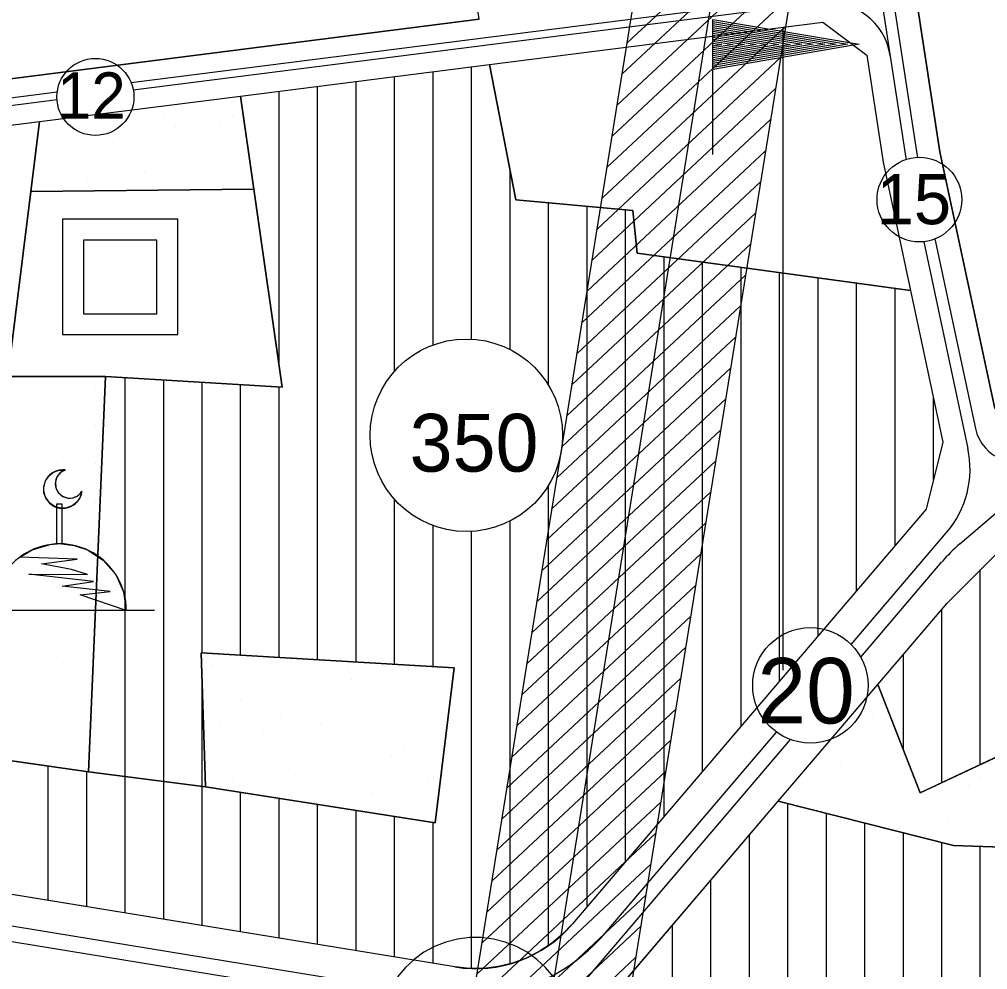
# Model space of a CAD drawing. Extents: x 419109 to 421295, y 4452223 to 4457798.
# Drawn here: x 419425.3 to 419676.8, y 4453192 to 4453438.7 of the extents above; entities that cross this region are included whole.
import ezdxf

# ---------------------------------------------------------------- set-up
doc = ezdxf.new("R2010")
doc.units = 0
for name, color, linetype in [('ADA', 7, 'Continuous'), ('ADAKENARI', 7, 'Continuous'), ('Default', 7, 'Continuous'), ('KALDIRIM', 7, 'Continuous'), ('KD_DAIRE', 7, 'Continuous'), ('KD_KAV_25', 7, 'Continuous'), ('KD_YGEN', 7, 'Continuous'), ('LJ_SEMBOL', 7, 'Continuous'), ('PL_AYA_PARK_DINLENME', 7, 'Continuous'), ('PL_KON_MEV_350', 7, 'Continuous'), ('PL_OZEL_DONATI', 7, 'Continuous'), ('PL_SAY_DINI_TESIS', 7, 'Continuous'), ('PL_SAY_SPOR', 7, 'Continuous'), ('SM_DAIRE', 7, 'Continuous'), ('SM_TAKS', 7, 'Continuous'), ('TA_ENH_154', 7, 'Continuous'), ('TA_ENH_KORUMA', 7, 'Continuous'), ('TA_ENH_TARAMA', 7, 'Continuous'), ('TR_DINITESIS', 7, 'Continuous'), ('TR_KENTSELSPOR', 7, 'Continuous'), ('TR_ORTAYOGUNKONUT', 7, 'Continuous'), ('TR_PARKALANI', 7, 'Continuous'), ('TR_PAZARLAMAAL', 7, 'Continuous'), ('TR_SAGLIKTESIS', 7, 'Continuous')]:
    doc.layers.add(name, color=color, linetype=linetype)

# ---------------------------------------------------------------- blocks, each defined once
blk = doc.blocks.new('POINT_DISPLAY')
at = {"layer": 'Default'}
blk.add_line((0, 0), (0, 0), dxfattribs=at)

msp = doc.modelspace()

# ---------------------------------------------------------------- linework, layer by layer
at = {"layer": 'ADA'}
for p, q in [((419547.38, 4453427.04), (419554.29, 4453391.85)), ((419486.2, 4453394.64), (419482.74, 4453418.83)), ((419430.49, 4453412.19), (419428.24, 4453394.01)), ((419428.24, 4453394.01), (419422.29, 4453346.02)), ((419428.24, 4453394.01), (419486.2, 4453394.64)), ((419493.54, 4453343.25), (419486.2, 4453394.64)), ((419554.29, 4453391.85), (419584.66, 4453389.09)), ((419584.66, 4453389.09), (419585.77, 4453378.05)), ((419585.77, 4453378.05), (419656.81, 4453368.31)), ((419447.7, 4453346.02), (419422.29, 4453346.02)), ((419443.28, 4453243.29), (419447.7, 4453346.02)), ((419447.7, 4453346.02), (419493.54, 4453343.25)), ((419538.27, 4453270.35), (419472.55, 4453274.22)), ((419472.55, 4453274.22), (419473.66, 4453239.43)), ((419533.3, 4453230.04), (419538.27, 4453270.35)), ((419648.28, 4453265.99), (419659.31, 4453237.86)), ((419659.31, 4453237.86), (419709.93, 4453261.66)), ((419405.17, 4453248.82), (419443.28, 4453243.29)), ((419473.66, 4453239.43), (419533.3, 4453230.04)), ((419667.92, 4453224.2), (419622.45, 4453235.7)), ((419710.94, 4453222.68), (419667.92, 4453224.2))]:
    msp.add_line(p, q, dxfattribs=at)
at = {"layer": 'ADAKENARI'}
for p, q in [((419664.45, 4453404.34), (419647.77, 4453512.81)), ((419544.76, 4453438.8), (419405.96, 4453421.17)), ((419547.38, 4453427.04), (419633.98, 4453438.04)), ((419633.98, 4453438.04), (419645.42, 4453429.42)), ((419645.42, 4453429.42), (419649.69, 4453401.63)), ((419482.74, 4453418.83), (419547.38, 4453427.04)), ((419430.49, 4453412.19), (419482.74, 4453418.83)), ((419407.47, 4453409.27), (419430.49, 4453412.19)), ((419678.69, 4453337.65), (419664.45, 4453404.34)), ((419649.69, 4453401.63), (419656.81, 4453368.31)), ((419656.81, 4453368.31), (419665.22, 4453328.9)), ((419665.22, 4453328.9), (419660.82, 4453311.51)), ((419660.82, 4453311.51), (419569.02, 4453203.86)), ((419666.3, 4453287.11), (419680.39, 4453301.22)), ((419648.28, 4453265.99), (419666.3, 4453287.11)), ((419622.45, 4453235.7), (419648.28, 4453265.99)), ((419538.42, 4453192.65), (419256.32, 4453238.73)), ((419512.36, 4453106.6), (419622.45, 4453235.7))]:
    msp.add_line(p, q, dxfattribs=at)
msp.add_arc((419543.77, 4453225.39), 33.18, 260.7236, 319.5427, dxfattribs=at)
at = {"layer": 'KALDIRIM'}
for p, q in [((419633.73, 4453564.67), (419658.55, 4453403.26)), ((419646.18, 4453463.94), (419655.59, 4453402.72)), ((419631.77, 4453444.81), (419454.34, 4453422.28)), ((419633.37, 4453443), (419454.89, 4453420.33)), ((419435.12, 4453419.84), (419406.59, 4453416.21)), ((419435.07, 4453417.81), (419406.84, 4453414.23)), ((419655.59, 4453402.72), (419655.66, 4453402.39)), ((419658.55, 4453403.26), (419658.62, 4453402.93)), ((419660.23, 4453381), (419671.69, 4453327.31)), ((419663.15, 4453381.71), (419673.65, 4453332.51)), ((419669.61, 4453302.53), (419750.92, 4453372.07)), ((419641.39, 4453276.4), (419666.16, 4453305.44)), ((419643.87, 4453273.14), (419664.97, 4453297.89)), ((419577.44, 4453201.41), (419621.99, 4453253.65)), ((419505.73, 4453111.15), (419625.6, 4453251.72)), ((419389.85, 4453208.81), (419533.58, 4453185.33)), ((419389.63, 4453204.79), (419519.06, 4453183.65))]:
    msp.add_line(p, q, dxfattribs=at)
for centre, radius, start, end in [((419635.42, 4453426.87), 16.27, 8.7413, 97.2392), ((419684.35, 4453334.79), 10.94, 192.0528, 310.5385), ((419646.76, 4453321.99), 25.5, 319.5427, 12.0528), ((419696.78, 4453270.77), 41.8, 130.5385, 139.5427), ((419541.25, 4453232.27), 47.56, 260.7236, 319.5427)]:
    msp.add_arc(centre, radius, start, end, dxfattribs=at)
at = {"layer": 'KD_DAIRE'}
for centre, radius in [((419445.04, 4453418.6), 10), ((419659.09, 4453391.94), 11), ((419630.79, 4453265.79), 15)]:
    msp.add_circle(centre, radius, dxfattribs=at)
at = {"layer": 'KD_KAV_25'}
for p, q in [((419539.1, 4453199.91), (419536.06, 4453199.13)), ((419542.21, 4453200.31), (419539.1, 4453199.91)), ((419545.35, 4453200.31), (419542.21, 4453200.31)), ((419548.47, 4453199.91), (419545.35, 4453200.31)), ((419551.51, 4453199.13), (419548.47, 4453199.91)), ((419533.14, 4453197.98), (419530.39, 4453196.46)), ((419536.06, 4453199.13), (419533.14, 4453197.98)), ((419554.43, 4453197.98), (419551.51, 4453199.13)), ((419557.18, 4453196.46), (419554.43, 4453197.98)), ((419530.39, 4453196.46), (419527.85, 4453194.62)), ((419559.72, 4453194.62), (419557.18, 4453196.46)), ((419525.56, 4453192.47), (419523.56, 4453190.05)), ((419527.85, 4453194.62), (419525.56, 4453192.47)), ((419562.01, 4453192.47), (419559.72, 4453194.62)), ((419564.01, 4453190.05), (419562.01, 4453192.47))]:
    msp.add_line(p, q, dxfattribs=at)
at = {"layer": 'LJ_SEMBOL'}
for p, q in [((419605.47, 4453403.68), (419605.47, 4453438.68)), ((419436.48, 4453386.86), (419436.48, 4453356.86)), ((419466.48, 4453386.86), (419436.48, 4453386.86)), ((419466.48, 4453356.86), (419466.48, 4453386.86)), ((419461.03, 4453381.4), (419441.94, 4453381.4)), ((419441.94, 4453381.4), (419441.94, 4453362.31)), ((419461.03, 4453362.31), (419461.03, 4453381.4)), ((419441.94, 4453362.31), (419461.03, 4453362.31)), ((419436.48, 4453356.86), (419466.48, 4453356.86)), ((419460.38, 4453285.21), (419413.71, 4453285.21))]:
    msp.add_line(p, q, dxfattribs=at)
for points in [[(419605.47, 4453438.68), (419643.42, 4453432.3), (419605.47, 4453425.73)], [(419605.47, 4453438.17), (419640.45, 4453432.29), (419605.47, 4453426.23)], [(419605.47, 4453437.66), (419637.47, 4453432.28), (419605.47, 4453426.74)], [(419605.47, 4453437.16), (419634.5, 4453432.28), (419605.47, 4453427.25)], [(419605.47, 4453436.65), (419631.53, 4453432.27), (419605.47, 4453427.76)], [(419605.47, 4453436.14), (419628.56, 4453432.26), (419605.47, 4453428.26)], [(419605.47, 4453435.64), (419625.59, 4453432.25), (419605.47, 4453428.77)], [(419605.47, 4453435.13), (419622.61, 4453432.25), (419605.47, 4453429.28)], [(419605.47, 4453434.62), (419619.64, 4453432.24), (419605.47, 4453429.79)], [(419605.47, 4453434.12), (419616.67, 4453432.23), (419605.47, 4453430.29)], [(419605.47, 4453433.61), (419613.7, 4453432.23), (419605.47, 4453430.8)], [(419605.47, 4453433.1), (419610.72, 4453432.22), (419605.47, 4453431.31)], [(419605.47, 4453432.59), (419607.75, 4453432.21), (419605.47, 4453431.82)]]:
    msp.add_lwpolyline(points, dxfattribs=at)
for points in [[(419436.48, 4453356.86), (419466.48, 4453356.86), (419466.48, 4453386.86), (419436.48, 4453386.86)], [(419441.55, 4453316.17), (419441.13, 4453314.66), (419440.26, 4453313.36), (419439.03, 4453312.39), (419437.56, 4453311.85), (419435.99, 4453311.79), (419434.48, 4453312.22), (419433.18, 4453313.09), (419432.22, 4453314.32), (419431.68, 4453315.79), (419431.62, 4453317.36), (419432.06, 4453318.87), (419432.93, 4453320.16), (419434.17, 4453321.13), (419435.64, 4453321.66), (419437.21, 4453321.71), (419435.95, 4453321.02), (419435.05, 4453319.91), (419434.64, 4453318.54), (419434.76, 4453317.11), (419435.41, 4453315.83), (419436.5, 4453314.89), (419437.85, 4453314.43), (419439.28, 4453314.51), (419440.58, 4453315.12)], [(419453.07, 4453285.22), (419441.09, 4453289.27), (419448.88, 4453290.19), (419436.44, 4453291.5), (419444.53, 4453292.76), (419427.78, 4453294.64), (419443.03, 4453294.57), (419438.86, 4453295.88), (419431.08, 4453297.32), (419440.3, 4453298.57), (419425.41, 4453299.09), (419428.58, 4453300.96), (419433.3, 4453302.35), (419435.05, 4453302.51), (419435.05, 4453312.93), (419436.3, 4453312.93), (419436.3, 4453302.52), (419439.54, 4453302.11), (419442.95, 4453300.96), (419447.1, 4453298.3), (419450.32, 4453294.58), (419452.37, 4453290.1)]]:
    msp.add_lwpolyline(points, close=True, dxfattribs=at)
for centre, radius, start, end in [((419436.59, 4453316.75), 5, 82.8556, 353.3219), ((419438.36, 4453318.15), 3.75, 107.9671, 328.2104), ((419435.77, 4453285.22), 17.31, 359.967, 180)]:
    msp.add_arc(centre, radius, start, end, dxfattribs=at)
at = {"layer": 'PL_AYA_PARK_DINLENME'}
for points in [[(419486.2, 4453394.64), (419428.24, 4453394.01), (419430.49, 4453412.19), (419482.74, 4453418.83)], [(419472.55, 4453274.22), (419538.27, 4453270.35), (419533.3, 4453230.04), (419473.66, 4453239.43)], [(419648.28, 4453265.99), (419659.31, 4453237.86), (419709.93, 4453261.66), (419710.94, 4453222.68), (419667.92, 4453224.2), (419622.45, 4453235.7)]]:
    msp.add_lwpolyline(points, close=True, dxfattribs=at)
at = {"layer": 'PL_KON_MEV_350'}
for points in [[(419665.01, 4453582.82), (419673.75, 4453518.14), (419647.77, 4453512.81), (419664.45, 4453404.34), (419678.69, 4453337.65), (419688.38, 4453334.37), (419743.12, 4453381.19)], [(419405.96, 4453421.17), (419544.76, 4453438.8), (419536.73, 4453492.22), (419575.78, 4453497.8), (419579.95, 4453471.41), (419597.04, 4453473.65), (419594.42, 4453493.65), (419591.8, 4453513.65), (419589.18, 4453533.65), (419587.39, 4453547.37), (419586.56, 4453553.65)], [(419405.17, 4453248.82), (419443.28, 4453243.29), (419473.66, 4453239.43), (419533.3, 4453230.04), (419538.27, 4453270.35), (419472.55, 4453274.22), (419473.66, 4453239.43), (419443.28, 4453243.29), (419447.7, 4453346.02), (419493.54, 4453343.25), (419486.2, 4453394.64), (419482.74, 4453418.83), (419547.38, 4453427.04), (419554.29, 4453391.85), (419584.66, 4453389.09), (419585.77, 4453378.05), (419656.81, 4453368.31), (419665.22, 4453328.9), (419660.82, 4453311.51), (419569.02, 4453203.86), (419566.4, 4453201.13), (419563.5, 4453198.71), (419560.33, 4453196.64), (419556.95, 4453194.94), (419553.4, 4453193.64), (419549.72, 4453192.75), (419545.97, 4453192.29), (419542.19, 4453192.25), (419538.42, 4453192.65), (419256.32, 4453238.73)], [(419407.47, 4453409.27), (419430.49, 4453412.19), (419428.24, 4453394.01), (419422.29, 4453346.02)], [(419709.93, 4453261.66), (419659.31, 4453237.86), (419648.28, 4453265.99), (419666.3, 4453287.11), (419680.39, 4453301.22)], [(419464.93, 4453019.07), (419512.36, 4453106.6), (419622.45, 4453235.7), (419667.92, 4453224.2), (419710.94, 4453222.68)]]:
    msp.add_lwpolyline(points, dxfattribs=at)
at = {"layer": 'PL_OZEL_DONATI'}
msp.add_lwpolyline([(419486.2, 4453394.64), (419493.54, 4453343.25), (419447.7, 4453346.02), (419422.29, 4453346.02), (419428.24, 4453394.01)], close=True, dxfattribs=at)
at = {"layer": 'PL_SAY_DINI_TESIS'}
msp.add_lwpolyline([(419447.7, 4453346.02), (419443.28, 4453243.29), (419405.17, 4453248.82), (419422.29, 4453346.02)], close=True, dxfattribs=at)
at = {"layer": 'PL_SAY_SPOR'}
msp.add_lwpolyline([(419547.38, 4453427.04), (419633.98, 4453438.04), (419645.42, 4453429.42), (419649.69, 4453401.63), (419656.81, 4453368.31), (419585.77, 4453378.05), (419584.66, 4453389.09), (419554.29, 4453391.85)], close=True, dxfattribs=at)
at = {"layer": 'SM_DAIRE'}
msp.add_circle((419541.41, 4453330.73), 25, dxfattribs=at)
at = {"layer": 'TA_ENH_154'}
msp.add_lwpolyline([(421244.23, 4452871.73), (420603.45, 4452866.93), (420104.11, 4452747.15), (419709.07, 4452649.72), (419353.3, 4452559.56), (419284.53, 4452601.29), (419287.68, 4452599.87), (419484.08, 4452691.72), (419833.95, 4454863.94), (419862.83, 4455014.24)], dxfattribs=at)
at = {"layer": 'TA_ENH_KORUMA'}
msp.add_line((419466.02, 4452705.35), (419814.25, 4454867.42), dxfattribs=at)
msp.add_lwpolyline([(419883.15, 4455014.02), (419853.65, 4454860.46), (419502.14, 4452678.09), (419329.55, 4452597.37), (419356.51, 4452581.01), (419704.22, 4452669.12), (420099.38, 4452766.58), (420601.01, 4452886.92), (421244.44, 4452891.74)], dxfattribs=at)
at = {"layer": 'TA_ENH_TARAMA'}
for p, q in [((419583.14, 4453432.57), (419630.84, 4453477.15)), ((419581.84, 4453424.52), (419629.54, 4453469.1)), ((419580.55, 4453416.46), (419628.25, 4453461.04)), ((419579.25, 4453408.4), (419626.95, 4453452.98)), ((419577.95, 4453400.35), (419625.65, 4453444.92)), ((419576.65, 4453392.29), (419624.35, 4453436.87)), ((419575.36, 4453384.23), (419623.05, 4453428.81)), ((419574.06, 4453376.17), (419621.76, 4453420.75)), ((419572.76, 4453368.12), (419620.46, 4453412.7)), ((419571.46, 4453360.06), (419619.16, 4453404.64)), ((419570.16, 4453352), (419617.86, 4453396.58)), ((419568.87, 4453343.95), (419616.57, 4453388.52)), ((419567.57, 4453335.89), (419615.27, 4453380.47)), ((419566.27, 4453327.83), (419613.97, 4453372.41)), ((419564.97, 4453319.77), (419612.67, 4453364.35)), ((419563.68, 4453311.72), (419611.38, 4453356.3)), ((419562.38, 4453303.66), (419610.08, 4453348.24)), ((419561.08, 4453295.6), (419608.78, 4453340.18)), ((419559.78, 4453287.55), (419607.48, 4453332.12)), ((419558.49, 4453279.49), (419606.18, 4453324.07)), ((419557.19, 4453271.43), (419604.89, 4453316.01)), ((419555.89, 4453263.37), (419603.59, 4453307.95)), ((419554.59, 4453255.32), (419602.29, 4453299.9)), ((419553.29, 4453247.26), (419600.99, 4453291.84)), ((419552, 4453239.2), (419599.7, 4453283.78)), ((419550.7, 4453231.15), (419598.4, 4453275.72)), ((419549.4, 4453223.09), (419597.1, 4453267.67)), ((419548.1, 4453215.03), (419595.8, 4453259.61)), ((419546.81, 4453206.97), (419594.51, 4453251.55)), ((419545.51, 4453198.92), (419593.21, 4453243.5)), ((419544.21, 4453190.86), (419591.91, 4453235.44)), ((419542.91, 4453182.8), (419590.61, 4453227.38)), ((419541.61, 4453174.75), (419589.31, 4453219.32)), ((419540.32, 4453166.69), (419588.02, 4453211.27)), ((419539.02, 4453158.63), (419586.72, 4453203.21)), ((419537.72, 4453150.57), (419585.42, 4453195.15))]:
    msp.add_line(p, q, dxfattribs=at)
at = {"layer": 'TR_ORTAYOGUNKONUT'}
for p, q in [((419542.78, 4453355.69), (419542.78, 4453426.46)), ((419522.78, 4453347.4), (419522.78, 4453423.91)), ((419532.78, 4453354.19), (419532.78, 4453425.18)), ((419502.78, 4453272.44), (419502.78, 4453421.37)), ((419512.78, 4453271.85), (419512.78, 4453422.64)), ((419492.78, 4453348.56), (419492.78, 4453420.1)), ((419552.78, 4453352.99), (419552.78, 4453399.53)), ((419562.78, 4453343.7), (419562.78, 4453391.08)), ((419572.78, 4453208.27), (419572.78, 4453390.17)), ((419582.78, 4453220), (419582.78, 4453389.26)), ((419592.78, 4453231.73), (419592.78, 4453377.09)), ((419602.78, 4453243.45), (419602.78, 4453375.71)), ((419612.78, 4453255.18), (419612.78, 4453374.34)), ((419622.78, 4453266.9), (419622.78, 4453372.97)), ((419632.78, 4453278.63), (419632.78, 4453371.6)), ((419642.78, 4453290.36), (419642.78, 4453370.23)), ((419652.78, 4453302.08), (419652.78, 4453368.86)), ((419452.78, 4453206.64), (419452.78, 4453345.71)), ((419462.78, 4453205), (419462.78, 4453345.11)), ((419472.78, 4453274.21), (419472.78, 4453344.5)), ((419482.78, 4453273.62), (419482.78, 4453343.9)), ((419492.78, 4453273.03), (419492.78, 4453343.3)), ((419662.78, 4453319.25), (419662.78, 4453340.33)), ((419562.78, 4453198.24), (419562.78, 4453317.75)), ((419522.78, 4453271.27), (419522.78, 4453314.06)), ((419552.78, 4453193.49), (419552.78, 4453308.46)), ((419532.78, 4453270.68), (419532.78, 4453307.27)), ((419542.78, 4453192.26), (419542.78, 4453305.77)), ((419674.93, 4453245.2), (419674.93, 4453295.76)), ((419664.93, 4453240.5), (419664.93, 4453285.51)), ((419654.93, 4453249.04), (419654.93, 4453273.78)), ((419472.78, 4453203.37), (419472.78, 4453267.01)), ((419432.78, 4453209.9), (419432.78, 4453244.81)), ((419442.78, 4453208.27), (419442.78, 4453243.37)), ((419482.78, 4453201.74), (419482.78, 4453237.99)), ((419492.78, 4453200.1), (419492.78, 4453236.42)), ((419624.93, 4453113.99), (419624.93, 4453235.07)), ((419502.78, 4453198.47), (419502.78, 4453234.84)), ((419512.78, 4453196.84), (419512.78, 4453233.27)), ((419634.93, 4453105.82), (419634.93, 4453232.54)), ((419522.78, 4453195.2), (419522.78, 4453231.69)), ((419532.78, 4453193.57), (419532.78, 4453230.12)), ((419644.93, 4452974.82), (419644.93, 4453230.01)), ((419614.93, 4453116.19), (419614.93, 4453226.88)), ((419654.93, 4452977.25), (419654.93, 4453227.48)), ((419664.93, 4452979.67), (419664.93, 4453224.95)), ((419674.93, 4452982.1), (419674.93, 4453223.95)), ((419604.93, 4453114.22), (419604.93, 4453215.15)), ((419594.93, 4453106.55), (419594.93, 4453203.42))]:
    msp.add_line(p, q, dxfattribs=at)
for points in [[(419800.26, 4453595.22), (419665.01, 4453582.82), (419673.75, 4453518.14), (419647.77, 4453512.81), (419664.45, 4453404.34), (419678.69, 4453337.65), (419688.38, 4453334.37), (419743.12, 4453381.19)], [(419405.96, 4453421.17), (419544.76, 4453438.8), (419536.73, 4453492.22), (419575.78, 4453497.8), (419579.95, 4453471.41), (419597.04, 4453473.65), (419594.42, 4453493.65), (419591.8, 4453513.65), (419589.18, 4453533.65), (419587.39, 4453547.37), (419586.56, 4453553.65)]]:
    msp.add_lwpolyline(points, dxfattribs=at)
at = {"layer": 'TR_PAZARLAMAAL'}
msp.add_line((419623.74, 4453269.75), (419623.74, 4453436.74), dxfattribs=at)

# ---------------------------------------------------------------- block references
at = {"layer": 'TR_DINITESIS', "xscale": 0.1, "yscale": 0.10000000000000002}
for p in [(419435.17, 4453343.29), (419445.17, 4453343.29), (419435.17, 4453333.29), (419445.17, 4453333.29), (419435.17, 4453323.29), (419445.17, 4453323.29), (419435.17, 4453313.29), (419445.17, 4453313.29), (419435.17, 4453303.29), (419445.17, 4453303.29), (419435.17, 4453293.29), (419445.17, 4453293.29), (419435.17, 4453283.29), (419435.17, 4453273.29), (419435.17, 4453263.29), (419435.17, 4453253.29)]:
    msp.add_blockref('POINT_DISPLAY', p, dxfattribs=at)
at = {"layer": 'TR_KENTSELSPOR', "xscale": 0.1, "yscale": 0.10000000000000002}
for p in [(419587.38, 4453408.31), (419627.38, 4453408.31)]:
    msp.add_blockref('POINT_DISPLAY', p, dxfattribs=at)
at = {"layer": 'TR_PARKALANI', "xscale": 0.1, "yscale": 0.10000000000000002}
for p in [(419462.78, 4453413.8), (419477.56, 4453411.2), (419480.67, 4453413.41), (419465.9, 4453410.81), (419451.12, 4453408.2), (419436.35, 4453405.6), (419472.56, 4453401.83), (419429.77, 4453399.32), (419453.89, 4453399.69), (419457.78, 4453399.22), (419460.18, 4453399.03), (419443.01, 4453396.62), (419444.54, 4453396.71), (419475.45, 4453271.17), (419495.8, 4453272.13), (419510.57, 4453269.52), (419526.43, 4453270), (419511.66, 4453267.4), (419518.59, 4453265.87), (419496.89, 4453264.79), (419482.11, 4453262.19), (419482.75, 4453261.91), (419533.09, 4453261.02), (419518.32, 4453258.42), (419493.19, 4453257.36), (419503.55, 4453255.81), (419507.1, 4453256.23), (419646.79, 4453257.43), (419477.55, 4453255.04), (419488.77, 4453253.21), (419474, 4453250.6), (419507.09, 4453249.83), (419524.98, 4453249.44), (419643.09, 4453250), (419653.45, 4453248.45), (419510.21, 4453246.83), (419521.87, 4453247.22), (419638.68, 4453245.85), (419495.43, 4453244.23), (419480.66, 4453241.62), (419531.64, 4453240.46), (419657, 4453242.47), (419674.88, 4453242.08), (419516.87, 4453237.85), (419534.04, 4453239.68), (419671.77, 4453239.86), (419498.2, 4453235.72), (419502.09, 4453235.25), (419504.49, 4453235.06), (419645.34, 4453236.87), (419630.56, 4453234.26), (419666.77, 4453230.49), (419654.39, 4453227.7)]:
    msp.add_blockref('POINT_DISPLAY', p, dxfattribs=at)
at = {"layer": 'TR_SAGLIKTESIS', "xscale": 0.1, "yscale": 0.10000000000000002}
for p in [(419442.29, 4453383.25), (419462.29, 4453383.25), (419482.29, 4453383.25), (419442.29, 4453363.25), (419462.29, 4453363.25), (419482.29, 4453363.25)]:
    msp.add_blockref('POINT_DISPLAY', p, dxfattribs=at)

# ---------------------------------------------------------------- texts
at = {"layer": 'KD_YGEN'}
for s, height, p in [('12', 12, (419435.07, 4453412.98)), ('15', 13, (419647.99, 4453385.54)), ('20', 17, (419617.03, 4453255.89))]:
    msp.add_text(s, height=height, dxfattribs=at).set_placement(p)
at = {"layer": 'SM_TAKS'}
msp.add_text('350', height=15, dxfattribs=at).set_placement((419526.67, 4453321.29))

doc.saveas('drawing.dxf')
